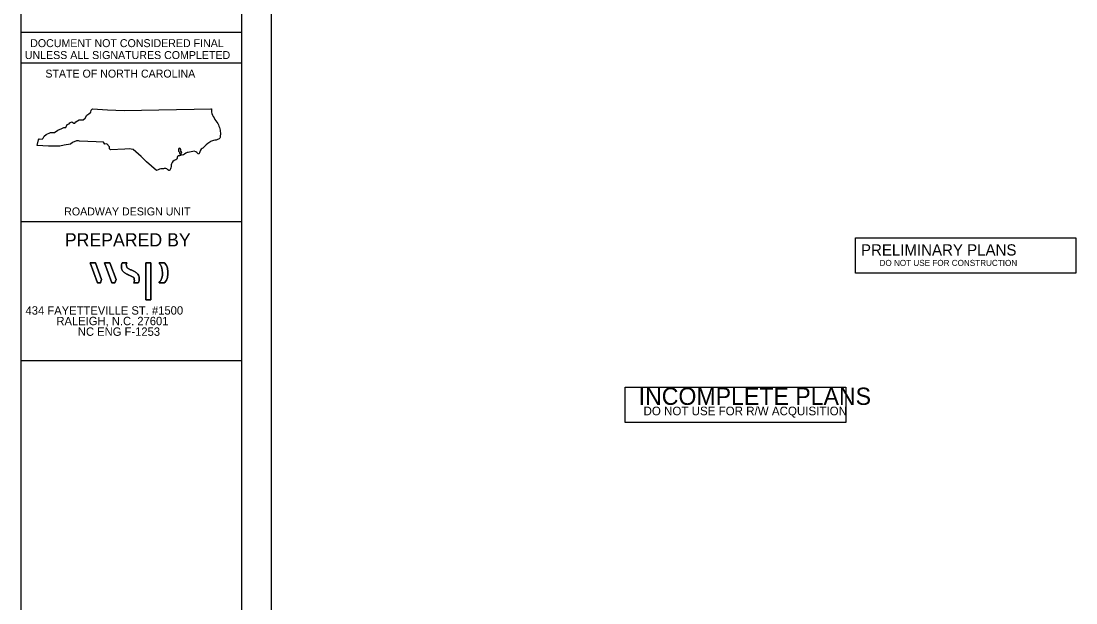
# Model space of a CAD drawing. Extents: x -0.56 to 3.44, y 0 to 1.83.
# Drawn here: x 2.644 to 3.441, y 0.917 to 1.357 of the extents above; entities that cross this region are included whole.
import ezdxf

# ---------------------------------------------------------------- set-up
doc = ezdxf.new("R2010")
doc.units = 0
for name, color, linetype in [('Default', 7, 'Continuous'), ('Old_Level_1', 7, 'Continuous'), ('Prop DSN Text', 7, 'Continuous'), ('Scratch_Level_0', 7, 'Continuous'), ('Sheet Plan CELL', 7, 'Continuous'), ('Sheet Sticker Incomplete CELL', 7, 'Continuous'), ('Sheet_Plan_CELL', 7, 'Continuous')]:
    doc.layers.add(name, color=color, linetype=linetype)

msp = doc.modelspace()

# ---------------------------------------------------------------- linework, layer by layer
at = {"layer": 'Default'}
msp.add_lwpolyline([(3.27474, 1.16611), (3.27474, 1.19275), (3.44141, 1.19275), (3.44141, 1.16611)], close=True, dxfattribs=at)
at = {"layer": 'Old_Level_1'}
msp.add_line((2.78784, 1.29033), (2.78783, 1.2904), dxfattribs=at)
for points in [[(2.65609, 1.26262), (2.65713, 1.26675), (2.65778, 1.2675), (2.66, 1.26735), (2.66076, 1.26807), (2.66135, 1.26969), (2.66301, 1.27098), (2.66612, 1.2724), (2.66939, 1.27243), (2.67171, 1.27405), (2.6748, 1.27543), (2.67633, 1.27625), (2.67783, 1.2763), (2.67884, 1.27856), (2.68032, 1.27898), (2.68081, 1.27978), (2.68239, 1.28052), (2.68382, 1.27946), (2.6846, 1.27954), (2.68549, 1.28035), (2.68781, 1.28203), (2.69099, 1.28206), (2.69242, 1.28329), (2.69364, 1.28556), (2.6952, 1.28664), (2.69664, 1.28775), (2.69695, 1.28926), (2.69788, 1.2904)], [(2.69788, 1.2904), (2.70928, 1.28959), (2.72187, 1.2891), (2.73493, 1.28926), (2.74826, 1.28949), (2.76137, 1.28972), (2.77492, 1.29012), (2.78746, 1.2904), (2.78783, 1.2904)], [(2.74649, 1.24377), (2.73875, 1.25013), (2.73482, 1.25421), (2.72877, 1.25944), (2.72564, 1.25994), (2.72235, 1.25978), (2.71153, 1.25925), (2.7109, 1.26004), (2.7109, 1.26084), (2.71085, 1.26164), (2.70886, 1.26382), (2.70732, 1.26363), (2.70626, 1.26512), (2.70071, 1.26527), (2.68815, 1.26583), (2.68736, 1.26598), (2.68586, 1.26599), (2.68276, 1.26488), (2.68126, 1.2637), (2.67666, 1.26273), (2.67339, 1.26198), (2.66464, 1.26209), (2.65609, 1.26262)]]:
    msp.add_lwpolyline(points, dxfattribs=at)
for points in [[(2.78784, 1.29033), (2.78802, 1.28788), (2.79263, 1.27911), (2.7943, 1.27521), (2.79466, 1.2712), (2.79446, 1.26862)], [(2.79446, 1.26862), (2.79408, 1.2678), (2.79336, 1.26737), (2.78945, 1.26629)], [(2.78945, 1.26629), (2.78659, 1.26516), (2.78136, 1.26066), (2.77934, 1.25843), (2.77833, 1.25614), (2.77609, 1.25785), (2.77131, 1.25741), (2.76958, 1.25718), (2.76576, 1.25537), (2.76503, 1.25592), (2.765, 1.25665), (2.76564, 1.25739), (2.76453, 1.25874), (2.7648, 1.25947), (2.76353, 1.26052), (2.7631, 1.25978), (2.76311, 1.25823), (2.76384, 1.25753), (2.7638, 1.25677), (2.76476, 1.25525), (2.76224, 1.25431), (2.76196, 1.25268), (2.75964, 1.25112), (2.75756, 1.24784), (2.75633, 1.24402), (2.75559, 1.24365), (2.75411, 1.24485), (2.75158, 1.24504), (2.75085, 1.24504), (2.74649, 1.24377)]]:
    msp.add_spline(points, degree=3, dxfattribs=at)
at = {"layer": 'Scratch_Level_0'}
msp.add_line((2.8333, 0), (2.8333, 1.8333), dxfattribs=at)
at = {"layer": 'Sheet Plan CELL'}
for p, q in [((2.81079, 1.34795), (2.64401, 1.34795)), ((2.81079, 1.32493), (2.64401, 1.32493)), ((2.81079, 1.20485), (2.64401, 1.20485)), ((2.81079, 1.20485), (2.64412, 1.20485)), ((2.81079, 1.09983), (2.64412, 1.09983))]:
    msp.add_line(p, q, dxfattribs=at)
at = {"layer": 'Sheet Sticker Incomplete CELL'}
msp.add_lwpolyline([(3.10072, 1.05316), (3.10072, 1.07981), (3.26739, 1.07981), (3.26739, 1.05316)], close=True, dxfattribs=at)
at = {"layer": 'Sheet_Plan_CELL'}
for p, q in [((2.64409, 0.0375), (2.64413, 1.7958)), ((2.81075, 0.0375), (2.81079, 1.7958)), ((2.70181, 1.15871), (2.69624, 1.17381)), ((2.69624, 1.17381), (2.7003, 1.17381)), ((2.7003, 1.17381), (2.70491, 1.16129)), ((2.71269, 1.15871), (2.70712, 1.17381)), ((2.70712, 1.17381), (2.71118, 1.17381)), ((2.71118, 1.17381), (2.71579, 1.16129)), ((2.73827, 1.14592), (2.73827, 1.17381)), ((2.73827, 1.17381), (2.74215, 1.17381)), ((2.74215, 1.17381), (2.74215, 1.14592)), ((2.70396, 1.15871), (2.70181, 1.15871)), ((2.70491, 1.16129), (2.70396, 1.15871)), ((2.71484, 1.15871), (2.71269, 1.15871)), ((2.71579, 1.16129), (2.71484, 1.15871)), ((2.74215, 1.14592), (2.73827, 1.14592))]:
    msp.add_line(p, q, dxfattribs=at)
for points in [[(2.7003, 1.17381), (2.69624, 1.17381), (2.70181, 1.15871), (2.70396, 1.15871), (2.70491, 1.16129), (2.7003, 1.17381)], [(2.71118, 1.17381), (2.70712, 1.17381), (2.71269, 1.15871), (2.71484, 1.15871), (2.71579, 1.16129), (2.71118, 1.17381)], [(2.74215, 1.14592), (2.74215, 1.17381), (2.73827, 1.17381), (2.73827, 1.14592), (2.74215, 1.14592)]]:
    msp.add_lwpolyline(points, dxfattribs=at)
for points in [[(2.71991, 1.17157), (2.71997, 1.17234), (2.72011, 1.1731), (2.72043, 1.17381), (2.72043, 1.17381), (2.72398, 1.17381), (2.72398, 1.17381), (2.72368, 1.17327), (2.72341, 1.17229), (2.72372, 1.17132), (2.72401, 1.17045), (2.72462, 1.16985), (2.72538, 1.16936), (2.72629, 1.16877), (2.72734, 1.16845), (2.72831, 1.168), (2.72933, 1.16752), (2.73032, 1.16703), (2.73118, 1.16629), (2.73241, 1.16521), (2.73316, 1.16394), (2.73329, 1.16229), (2.7333, 1.1621), (2.73331, 1.1619), (2.73331, 1.1617), (2.73331, 1.16067), (2.73315, 1.15965), (2.73269, 1.15872), (2.73269, 1.15872), (2.72904, 1.15872), (2.72904, 1.15872), (2.7294, 1.15933), (2.72968, 1.16016), (2.72963, 1.16092), (2.7295, 1.16282), (2.72718, 1.16386), (2.72524, 1.16473), (2.72494, 1.16486), (2.72465, 1.16499), (2.72437, 1.16512), (2.72352, 1.16552), (2.72268, 1.16598), (2.72195, 1.16659), (2.72119, 1.16721), (2.72062, 1.16784), (2.72027, 1.16876), (2.71996, 1.16956), (2.71985, 1.17044), (2.71989, 1.1713), (2.71989, 1.17139), (2.7199, 1.17148), (2.71991, 1.17157)], [(2.71991, 1.17157), (2.7199, 1.17148), (2.71989, 1.17139), (2.71989, 1.1713), (2.71985, 1.17044), (2.71996, 1.16956), (2.72027, 1.16876), (2.72062, 1.16784), (2.72119, 1.16721), (2.72195, 1.16659), (2.72268, 1.16598), (2.72352, 1.16552), (2.72437, 1.16512), (2.72465, 1.16499), (2.72494, 1.16486), (2.72524, 1.16473), (2.72718, 1.16386), (2.7295, 1.16282), (2.72963, 1.16092), (2.72968, 1.16016), (2.7294, 1.15933), (2.72904, 1.15872), (2.72904, 1.15872), (2.73269, 1.15872), (2.73269, 1.15872), (2.73315, 1.15965), (2.73331, 1.16067), (2.73331, 1.1617), (2.73331, 1.1619), (2.7333, 1.1621), (2.73329, 1.16229), (2.73316, 1.16394), (2.73241, 1.16521), (2.73118, 1.16629), (2.73032, 1.16703), (2.72933, 1.16752), (2.72831, 1.168), (2.72734, 1.16845), (2.72629, 1.16877), (2.72538, 1.16936), (2.72462, 1.16985), (2.72401, 1.17045), (2.72372, 1.17132), (2.72341, 1.17229), (2.72368, 1.17327), (2.72398, 1.17381), (2.72398, 1.17381), (2.72043, 1.17381), (2.72043, 1.17381), (2.72011, 1.1731), (2.71997, 1.17234), (2.71991, 1.17157)], [(2.75083, 1.16627), (2.75083, 1.16944), (2.74967, 1.17208), (2.74815, 1.17381), (2.74815, 1.17381), (2.75255, 1.17381), (2.75255, 1.17381), (2.754, 1.17205), (2.75489, 1.16906), (2.75489, 1.16627), (2.75489, 1.16627), (2.75489, 1.16626), (2.75489, 1.16626), (2.75489, 1.16347), (2.75399, 1.16047), (2.75255, 1.15872), (2.75255, 1.15872), (2.74815, 1.15872), (2.74815, 1.15872), (2.74967, 1.16045), (2.75083, 1.16309), (2.75083, 1.16626), (2.75083, 1.16626), (2.75083, 1.16627), (2.75083, 1.16627)], [(2.75083, 1.16627), (2.75083, 1.16627), (2.75083, 1.16626), (2.75083, 1.16626), (2.75083, 1.16309), (2.74967, 1.16045), (2.74815, 1.15872), (2.74815, 1.15872), (2.75255, 1.15872), (2.75255, 1.15872), (2.75399, 1.16047), (2.75489, 1.16347), (2.75489, 1.16626), (2.75489, 1.16626), (2.75489, 1.16627), (2.75489, 1.16627), (2.75489, 1.16906), (2.754, 1.17205), (2.75255, 1.17381), (2.75255, 1.17381), (2.74815, 1.17381), (2.74815, 1.17381), (2.74967, 1.17208), (2.75083, 1.16944), (2.75083, 1.16627)]]:
    msp.add_open_spline(points, degree=3, dxfattribs=at)

# ---------------------------------------------------------------- texts
at = {"layer": 'Default'}
for s, height, p in [('PREPARED BY', 0.0100002, (2.67708, 1.18623)), ('434 FAYETTEVILLE ST. #1500 ', 0.0063344, (2.64738, 1.13467)), ('RALEIGH, N.C. 27601', 0.0063344, (2.67069, 1.12666)), ('NC ENG F-1253', 0.0063344, (2.68692, 1.11865))]:
    msp.add_text(s, height=height, dxfattribs=at).set_placement(p)
at = {"layer": 'Prop DSN Text'}
for s, p in [('DOCUMENT NOT CONSIDERED FINAL', (2.65088, 1.33698)), ('UNLESS ALL SIGNATURES COMPLETED', (2.64682, 1.32797)), ('STATE OF NORTH CAROLINA', (2.66236, 1.31395)), ('ROADWAY DESIGN UNIT', (2.67659, 1.20969))]:
    msp.add_text(s, height=0.0060039, dxfattribs=at).set_placement(p)
at = {"layer": 'Sheet Sticker Incomplete CELL'}
for s, height, p in [('PRELIMINARY PLANS', 0.0085035, (3.27893, 1.17937)), ('DO NOT USE FOR CONSTRUCTION', 0.0045919, (3.29297, 1.17149)), ('INCOMPLETE PLANS', 0.0130617, (3.11087, 1.06643)), ('DO NOT USE FOR R/W ACQUISITION', 0.0065308, (3.11455, 1.05855))]:
    msp.add_text(s, height=height, dxfattribs=at).set_placement(p)

doc.saveas('drawing.dxf')
